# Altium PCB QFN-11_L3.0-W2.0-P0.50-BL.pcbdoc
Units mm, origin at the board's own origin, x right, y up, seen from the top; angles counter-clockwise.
Board outline 15.99 x 15.43 mm, 2 copper layers (Top Layer, Bottom Layer), stack 0 mm thick; 1 components, 0 nets, 11 pads, 0 vias.
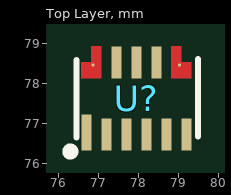
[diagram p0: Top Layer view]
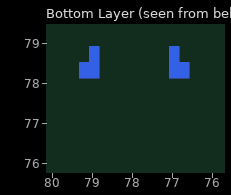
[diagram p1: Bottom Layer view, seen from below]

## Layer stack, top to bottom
Top Layer: signal copper (thickness not stored)
Bottom Layer: signal copper (thickness not stored)

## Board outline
85.84,69.85 69.85,69.85 69.85,85.28 85.84,85.28

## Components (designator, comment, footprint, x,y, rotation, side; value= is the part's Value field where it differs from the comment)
U? "" QFN-11_L3.0-W2.0-P0.50-BL 77.95,77.63 r0 top

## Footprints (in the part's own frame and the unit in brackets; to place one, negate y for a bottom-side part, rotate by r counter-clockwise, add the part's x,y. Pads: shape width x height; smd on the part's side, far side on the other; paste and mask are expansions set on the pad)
QFN-11_L3.0-W2.0-P0.50-BL [mm]
  rect 0.25x0.9 smd: 1(-1.25,-0.85)
  rect 0.25x0.8 smd: 2(-0.75,-0.9) 3(-0.25,-0.9) 4(0.25,-0.9) 5(0.75,-0.9) 6(1.25,-0.9) 8(0.5,0.9) 9(0,0.9) 10(-0.5,0.9)
  round 0.079 smd: 7(1.083,0.833) 11(-1.083,0.833)
  Top Layer region: -1.375,0.5 -1.375,0.9 -1.125,0.9 -1.125,1.3 -0.875,1.3 -0.875,0.5
  Top Layer region: 0.875,0.5 0.875,1.3 1.125,1.3 1.125,0.9 1.375,0.9 1.375,0.5 1.125,0.5
  Bottom Layer region: -1.375,0.5 -1.375,0.9 -1.125,0.9 -1.125,1.3 -0.875,1.3 -0.875,0.5
  Bottom Layer region: 0.875,0.5 0.875,1.3 1.125,1.3 1.125,0.9 1.375,0.9 1.375,0.5 1.125,0.5
  Multi-Layer region: -1.375,0.5 -1.375,0.9 -1.125,0.9 -1.125,1.3 -0.875,1.3 -0.875,0.5
  Multi-Layer region: 0.875,0.5 0.875,1.3 1.125,1.3 1.125,0.9 1.375,0.9 1.375,0.5 1.125,0.5
  silkscreen extent -1.75,-1.43 1.54,0.98

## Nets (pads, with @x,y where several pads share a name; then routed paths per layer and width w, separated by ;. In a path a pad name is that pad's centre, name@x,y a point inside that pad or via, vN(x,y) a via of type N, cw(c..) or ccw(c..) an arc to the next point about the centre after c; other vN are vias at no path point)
pads on no net: U?.1 U?.2 U?.3 U?.4 U?.5 U?.6 U?.7 U?.8 U?.9 U?.10 U?.11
